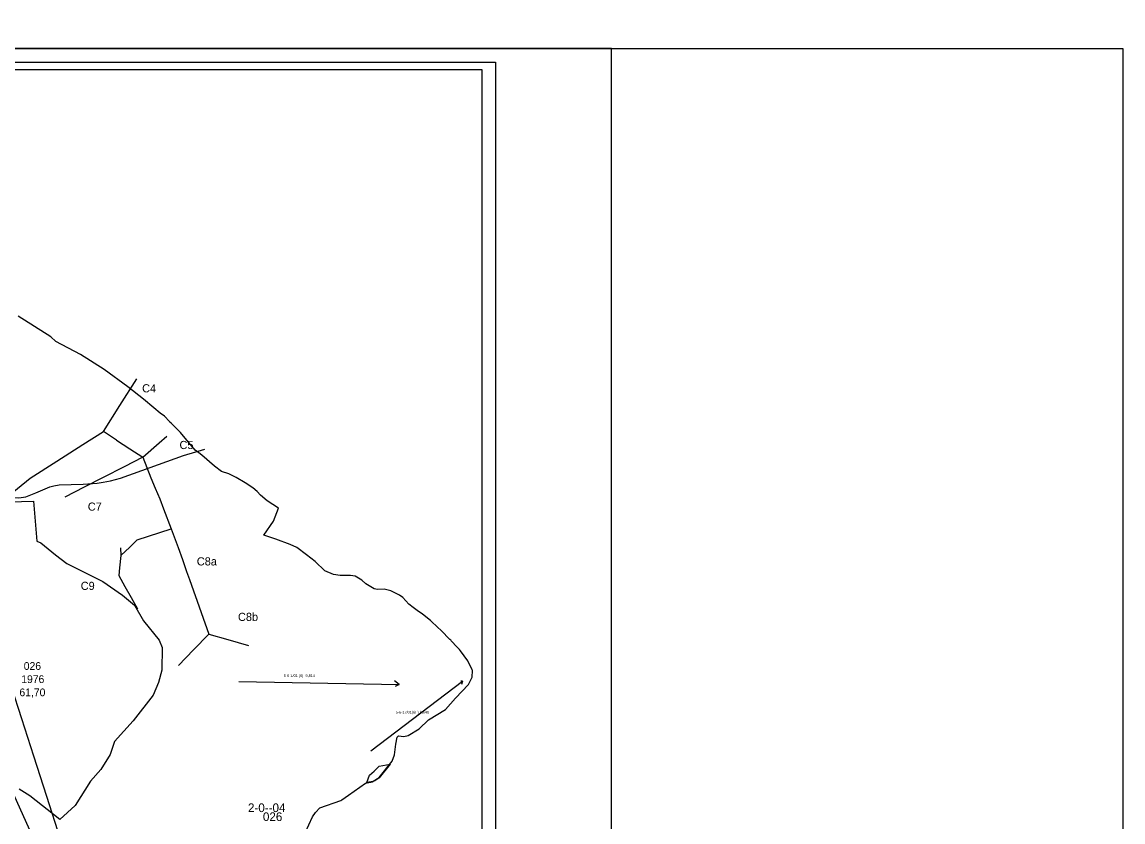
# Model space of a CAD drawing. Extents: x -557103 to -548162, y -1041918 to -1033974.
# Drawn here: x -552210 to -548162, y -1037449 to -1034507 of the extents above; entities that cross this region are included whole.
import ezdxf

# ---------------------------------------------------------------- set-up
doc = ezdxf.new("R2010")
doc.units = 0
for name, color, linetype in [('body1', 7, 'Continuous'), ('body3', 7, 'Continuous'), ('Rámeček', 7, 'Continuous'), ('Vrstva 11', 7, 'Continuous'), ('Vrstva 14', 7, 'Continuous'), ('Vrstva 15', 7, 'Continuous'), ('Vrstva 16', 7, 'Continuous'), ('Vrstva 37', 7, 'Continuous'), ('Vrstva 63', 7, 'Continuous'), ('Vrstva 9', 7, 'Continuous')]:
    doc.layers.add(name, color=color, linetype=linetype)

msp = doc.modelspace()

# ---------------------------------------------------------------- linework, layer by layer
at = {"layer": 'body1'}
msp.add_lwpolyline([(-550469.3, -1040018.6), (-555211.6, -1040018.6), (-555211.6, -1034654.7), (-550469.3, -1034654.7)], close=True, dxfattribs=at)
at = {"layer": 'body3'}
for p, q in [((-552104, -1035665.4), (-552223.9, -1035589.2)), ((-552086.2, -1035681.9), (-552104, -1035665.4)), ((-551994.8, -1035729.5), (-552086.2, -1035681.9)), ((-551908.1, -1035784.8), (-551994.8, -1035729.5)), ((-551821.4, -1035848.3), (-551908.1, -1035784.8)), ((-551762.8, -1035894.5), (-551821.4, -1035848.3)), ((-551725, -1035926.4), (-551762.8, -1035894.5)), ((-551702.3, -1035945.6), (-551725, -1035926.4)), ((-551685.8, -1035956.4), (-551702.3, -1035945.6)), ((-551668.2, -1035976), (-551685.8, -1035956.4)), ((-551666.1, -1035978.4), (-551668.2, -1035976)), ((-551662.1, -1035982.8), (-551666.1, -1035978.4)), ((-551639.8, -1036005), (-551662.1, -1035982.8)), ((-551627.8, -1036016.9), (-551639.8, -1036005)), ((-551573.2, -1036081.2), (-551627.8, -1036016.9)), ((-551560.5, -1036091.2), (-551573.2, -1036081.2)), ((-551548.3, -1036100.5), (-551560.5, -1036091.2)), ((-551502.6, -1036140), (-551548.3, -1036100.5)), ((-551476.3, -1036159.9), (-551502.6, -1036140)), ((-551449.1, -1036168.6), (-551476.3, -1036159.9)), ((-551422.9, -1036181.8), (-551449.1, -1036168.6)), ((-551389.7, -1036201.8), (-551422.9, -1036181.8)), ((-551360.8, -1036220.6), (-551389.7, -1036201.8)), ((-551346, -1036233.8), (-551360.8, -1036220.6)), ((-551333.8, -1036247.7), (-551346, -1036233.8)), ((-551309.1, -1036267.8), (-551333.8, -1036247.7)), ((-551267, -1036294.6), (-551309.1, -1036267.8)), ((-551286, -1036343.4), (-551267, -1036294.6)), ((-551320.9, -1036394.6), (-551286, -1036343.4)), ((-551276.8, -1036409.4), (-551320.9, -1036394.6)), ((-551223.8, -1036428.1), (-551276.8, -1036409.4)), ((-551200, -1036439.7), (-551223.8, -1036428.1)), ((-551164, -1036467), (-551200, -1036439.7)), ((-551132.3, -1036491.4), (-551164, -1036467)), ((-551096.1, -1036526.1), (-551132.3, -1036491.4)), ((-551064.4, -1036538.7), (-551096.1, -1036526.1)), ((-551040.6, -1036543.1), (-551064.4, -1036538.7)), ((-551002.2, -1036543.2), (-551040.6, -1036543.1)), ((-550985.7, -1036544.8), (-551002.2, -1036543.2)), ((-550960, -1036560), (-550985.7, -1036544.8)), ((-550945.3, -1036573.3), (-550960, -1036560)), ((-550915.1, -1036591.1), (-550945.3, -1036573.3)), ((-550902.7, -1036594.3), (-550915.1, -1036591.1)), ((-550878.1, -1036593.1), (-550902.7, -1036594.3)), ((-550854.2, -1036599.3), (-550878.1, -1036593.1)), ((-550822.5, -1036614.5), (-550854.2, -1036599.3)), ((-550809.9, -1036623.2), (-550822.5, -1036614.5)), ((-550787.9, -1036647.6), (-550809.9, -1036623.2)), ((-550771.6, -1036660.3), (-550787.9, -1036647.6)), ((-550751.7, -1036674.6), (-550771.6, -1036660.3)), ((-550738.2, -1036683.6), (-550751.7, -1036674.6)), ((-550718.6, -1036700), (-550738.2, -1036683.6)), ((-550708.7, -1036708.4), (-550718.6, -1036700)), ((-550703.6, -1036712.8), (-550708.7, -1036708.4)), ((-550667, -1036747.7), (-550703.6, -1036712.8)), ((-550639.6, -1036775.1), (-550667, -1036747.7)), ((-550636.7, -1036778.2), (-550639.6, -1036775.1)), ((-550633.9, -1036781.1), (-550636.7, -1036778.2)), ((-550632.5, -1036782.5), (-550633.9, -1036781.1)), ((-550630.4, -1036784.7), (-550632.5, -1036782.5)), ((-550628.4, -1036786.8), (-550630.4, -1036784.7)), ((-550613.6, -1036802.3), (-550628.4, -1036786.8)), ((-550608.8, -1036807.4), (-550613.6, -1036802.3)), ((-550601.8, -1036814.7), (-550608.8, -1036807.4)), ((-550597.6, -1036819.7), (-550601.8, -1036814.7)), ((-550570.8, -1036856.5), (-550597.6, -1036819.7)), ((-550555.1, -1036889.3), (-550570.8, -1036856.5)), ((-550568.4, -1036943.8), (-550555.5, -1036916.2)), ((-550555.5, -1036916.2), (-550553.6, -1036892.5)), ((-550553.6, -1036892.5), (-550555.1, -1036889.3)), ((-550616.6, -1036993.9), (-550568.4, -1036943.8)), ((-550652.8, -1037035.8), (-550616.6, -1036993.9)), ((-550716, -1037073.7), (-550652.8, -1037035.8)), ((-550749.6, -1037106.8), (-550716, -1037073.7)), ((-550790.7, -1037131.1), (-550749.6, -1037106.8)), ((-550840.7, -1037202.1), (-550836, -1037162.6)), ((-550836, -1037162.6), (-550830.5, -1037137.8)), ((-550830.5, -1037137.8), (-550826, -1037132.2)), ((-550826, -1037132.2), (-550806.3, -1037134.3)), ((-550806.3, -1037134.3), (-550790.7, -1037131.1)), ((-550848.5, -1037225.6), (-550840.7, -1037202.1)), ((-550896.3, -1037286.1), (-550848.5, -1037225.6)), ((-550912.9, -1037296.1), (-550896.3, -1037286.1)), ((-551009.4, -1037350.1), (-550947.5, -1037306.8)), ((-550947.5, -1037306.8), (-550921.2, -1037301)), ((-550921.2, -1037301), (-550912.9, -1037296.1)), ((-551037.9, -1037370.2), (-551033.6, -1037367.2)), ((-551033.6, -1037367.2), (-551009.4, -1037350.1)), ((-551130.6, -1037413.7), (-551114.5, -1037397)), ((-551114.5, -1037397), (-551037.9, -1037370.2)), ((-551169.3, -1037488.5), (-551141.4, -1037429.8)), ((-551141.4, -1037429.8), (-551130.6, -1037413.7))]:
    msp.add_line(p, q, dxfattribs=at)
at = {"layer": 'Rámeček'}
for points in [[(-555307.9, -1039662.1), (-550042, -1039662.1), (-550042, -1034604.4), (-555307.9, -1034604.4)], [(-555307.9, -1034604.4), (-548161.9, -1034604.4), (-548161.9, -1039661.8), (-555307.9, -1039661.8)]]:
    msp.add_lwpolyline(points, close=True, dxfattribs=at)
at = {"layer": 'Vrstva 11'}
for p, q in [((-550823.5, -1036943.3), (-550838.2, -1036950.7)), ((-550590.1, -1036931.3), (-550594.7, -1036943.3))]:
    msp.add_line(p, q, dxfattribs=at)
for points in [[(-551413.3, -1036932.3), (-550823.5, -1036943.3), (-550841, -1036929.5)], [(-550927.8, -1037187.2), (-550590.1, -1036931.3), (-550596.5, -1036931.3)]]:
    msp.add_lwpolyline(points, dxfattribs=at)
at = {"layer": 'Vrstva 14'}
msp.add_lwpolyline([(-551661.8, -1038633.9), (-553519.6, -1034507.2), (-553504.9, -1034676.5)], dxfattribs=at)
at = {"layer": 'Vrstva 15'}
msp.add_line((-551862.5, -1036044.4), (-551910.2, -1036013.3), dxfattribs=at)
for points in [[(-552393.7, -1036360.2), (-552349.6, -1036323.5), (-552259.7, -1036249.6), (-552180, -1036184.8), (-552081.6, -1036122.4), (-551986.3, -1036061.3), (-551910.2, -1036013.3), (-551850.2, -1035917.9), (-551788.1, -1035819.1)], [(-551766.2, -1036107.7), (-551706.2, -1036055), (-551678.2, -1036030.2)], [(-551862.5, -1036044.4), (-551813.2, -1036076.5), (-551766.2, -1036107.7), (-551736.1, -1036182.9), (-551719.9, -1036221.4), (-551703.9, -1036260.7), (-551689.5, -1036297.4), (-551661.1, -1036370.9), (-551635.9, -1036439.2), (-551620.3, -1036483.3), (-551604.7, -1036527.7), (-551594.3, -1036557.2), (-551551.3, -1036678.7), (-551523.6, -1036758.5), (-551452.8, -1036778.4), (-551377, -1036799.8)], [(-551766.2, -1036107.7), (-551834.1, -1036143.3), (-551911.4, -1036182.4), (-551981.4, -1036218.1), (-552052.9, -1036254.3)], [(-551846.3, -1036468.8), (-551813.8, -1036437.9), (-551786.4, -1036411.8), (-551661.1, -1036370.9)], [(-551848.3, -1036441.1), (-551846.3, -1036468.8), (-551851.3, -1036514.8), (-551854.5, -1036543), (-551831.6, -1036583.6), (-551808.9, -1036624.1), (-551786, -1036665.8)], [(-551523.6, -1036758.5), (-551579.4, -1036815.8), (-551635, -1036873.3)], [(-552068.1, -1037512.6), (-552118.7, -1037355.6), (-552166.5, -1037207.2), (-552210.9, -1037069.8), (-552249.3, -1036951.7), (-552280.1, -1036856.3), (-552310.8, -1036764.1)]]:
    msp.add_lwpolyline(points, dxfattribs=at)
at = {"layer": 'Vrstva 63'}
msp.add_lwpolyline([(-550519.3, -1039635.9), (-556362.3, -1039635.9), (-556362.3, -1034682.3), (-550519.3, -1034682.3)], close=True, dxfattribs=at)
at = {"layer": 'Vrstva 9'}
for points in [[(-552422.7, -1036299.6), (-552361.3, -1036275.1), (-552316.3, -1036260.2), (-552294, -1036255.5), (-552265.3, -1036255.9), (-552222.2, -1036256.5), (-552195.9, -1036253.5), (-552159.2, -1036238.6), (-552108, -1036216.6), (-552092.7, -1036213.1), (-552073.9, -1036209.4), (-551985.6, -1036206.8), (-551933.9, -1036203.5), (-551911.7, -1036200), (-551885, -1036194.9), (-551848.3, -1036184.3), (-551769.3, -1036156.4), (-551616.1, -1036101.3), (-551537.4, -1036078.2)], [(-552343.8, -1036274.8), (-552167.6, -1036269.4), (-552155.2, -1036416.7), (-552140.5, -1036423), (-552086.8, -1036466.2), (-552045.4, -1036498.2), (-551912.4, -1036565), (-551840.7, -1036615.6), (-551796.5, -1036651.5), (-551763.4, -1036709.5), (-551705.4, -1036780.4), (-551694.4, -1036808), (-551696.2, -1036890.8), (-551708.2, -1036935.9), (-551728.3, -1036982.2), (-551801.8, -1037077.1), (-551869.9, -1037152.6), (-551886.5, -1037200.5), (-551920.5, -1037256.3), (-551958.3, -1037299.6), (-552014.4, -1037388), (-552071.4, -1037439.7), (-552181.9, -1037352.7), (-552220.5, -1037328.8)]]:
    msp.add_lwpolyline(points, dxfattribs=at)
msp.add_lwpolyline([(-550942.4, -1037304.2), (-550932.3, -1037277.5), (-550914.8, -1037261.9), (-550896.4, -1037244.4), (-550856.8, -1037236.1), (-550896.3, -1037286.2), (-550918.8, -1037299.7)], close=True, dxfattribs=at)

# ---------------------------------------------------------------- texts
at = {"layer": 'Vrstva 11'}
for s, p in [('5-6-1/01 (6)  9,814', (-551247.6, -1036916.1)), ('5-6-17/01(6F) 0,640', (-550835.9, -1037050.5))]:
    msp.add_text(s, height=10, dxfattribs=at).set_placement(p)
at = {"layer": 'Vrstva 16'}
for s, p in [('2-0--04', (-551379.3, -1037412.7)), ('026', (-551324.3, -1037445.7))]:
    msp.add_text(s, height=32, dxfattribs=at).set_placement(p)
at = {"layer": 'Vrstva 37'}
for s, p in [('C4', (-551768.4, -1035869.3)), ('C5', (-551631, -1036077.7)), ('C7', (-551968.1, -1036304.4)), ('C8a', (-551567.3, -1036505.7)), ('C9', (-551994.1, -1036595.7)), ('C8b', (-551415.8, -1036709.9))]:
    msp.add_text(s, height=30, dxfattribs=at).set_placement(p)
at = {"layer": 'Vrstva 9'}
for s, p in [('026', (-552203.7, -1036889.7)), ('1976', (-552212.9, -1036938.2)), ('61,70', (-552219.5, -1036986.7))]:
    msp.add_text(s, height=28.5, dxfattribs=at).set_placement(p)

doc.saveas('drawing.dxf')
